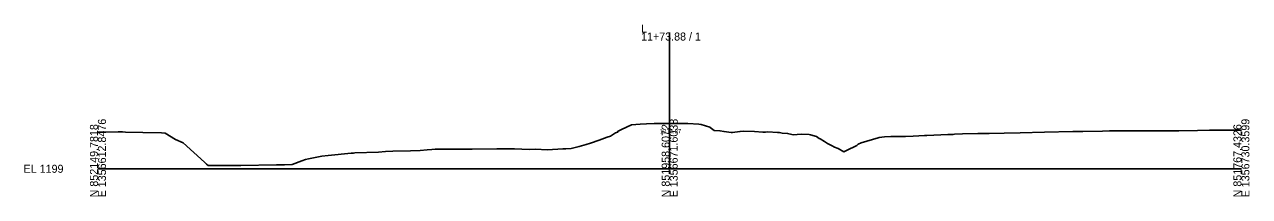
# Model space of a CAD drawing. Extents: x -26 to 4603, y -10 to 4066.
# Drawn here: x 2774.3 to 3202.8, y -9.7 to 50.4 of the extents above; entities that cross this region are included whole.
import ezdxf

# ---------------------------------------------------------------- set-up
doc = ezdxf.new("R2010")
doc.units = 0
for name, color, linetype in [('Exist Cross Section Cell', 7, 'Continuous'), ('Exist XS Center Line Elevation Label', 7, 'Continuous'), ('Exist XS Ground Line', 7, 'Continuous')]:
    doc.layers.add(name, color=color, linetype=linetype)

msp = doc.modelspace()

# ---------------------------------------------------------------- linework, layer by layer
at = {"layer": 'Exist Cross Section Cell'}
for p, q in [((3000, 0), (3000, 47.64)), ((2800, 0), (3000, 0)), ((3000, 0), (3200, 0))]:
    msp.add_line(p, q, dxfattribs=at)
at = {"layer": 'Exist XS Ground Line'}
msp.add_lwpolyline([(2800, 12.76), (2807.09, 12.86), (2807.69, 12.88), (2808.59, 12.87), (2809.67, 12.85), (2815.73, 12.71), (2822.26, 12.54), (2823.51, 12.48), (2827.12, 10.28), (2829.77, 9.06), (2837.31, 2.28), (2837.94, 1.59), (2838.6, 1.12), (2849.94, 1.13), (2862.42, 1.36), (2865.31, 1.41), (2868, 1.45), (2871.3, 2.72), (2872.57, 3.29), (2873.63, 3.45), (2878.33, 4.42), (2880.49, 4.66), (2888.59, 5.45), (2889.38, 5.51), (2889.82, 5.52), (2898.14, 5.85), (2900.58, 6.01), (2903.2, 6.1), (2909.37, 6.24), (2912.75, 6.44), (2915.12, 6.67), (2916.79, 6.79), (2917.93, 6.81), (2922.91, 6.83), (2928.5, 6.81), (2930.95, 6.8), (2939.49, 7), (2940.97, 7.02), (2942.05, 7.02), (2943.57, 6.97), (2945.72, 6.94), (2950.84, 6.71), (2952.92, 6.83), (2957.26, 6.64), (2962.57, 6.92), (2963.68, 6.92), (2965.5, 7.05), (2968.34, 7.84), (2970.78, 8.47), (2972.29, 8.94), (2975.29, 9.98), (2978.17, 11), (2979.25, 11.36), (2981.06, 12.57), (2981.77, 12.78), (2981.97, 13.19), (2983.14, 13.78), (2986.61, 15.39), (2989.65, 15.65), (2991.9, 15.71), (2994.62, 15.83), (2998.58, 15.88), (3000, 15.87), (3002.99, 15.86), (3006.39, 15.83), (3010.16, 15.54), (3011.04, 15.48), (3014.02, 14.51), (3014.17, 14.4), (3015.56, 13.35), (3017.56, 13.32), (3019.04, 13.02), (3020.71, 12.77), (3021.56, 12.68), (3022.03, 12.7), (3024.59, 12.98), (3025.85, 13.19), (3029.66, 13.05), (3032.63, 12.84), (3033.48, 12.85), (3034.29, 12.86), (3037.69, 12.73), (3038.42, 12.72), (3039.39, 12.48), (3041.25, 12.34), (3042.69, 12.03), (3043.24, 11.88), (3045.97, 12.11), (3048.85, 11.97), (3049.26, 11.84), (3051.33, 11.33), (3052.27, 10.59), (3052.69, 10.43), (3054.15, 9.5), (3055.19, 8.82), (3056.82, 8.02), (3057.66, 7.52), (3058.94, 7.06), (3060.91, 5.97), (3061.81, 6.4), (3065.53, 8.11), (3065.96, 8.61), (3067.02, 9.09), (3071, 10.26), (3072.9, 10.84), (3073.34, 10.94), (3075.14, 11.18), (3077.34, 11.24), (3082.48, 11.33), (3085.21, 11.38), (3089.11, 11.59), (3089.96, 11.66), (3097.28, 11.95), (3098.3, 12.01), (3098.71, 12.02), (3099.23, 12.03), (3099.69, 12.04), (3102.39, 12.19), (3107.75, 12.36), (3111.73, 12.38), (3117.03, 12.43), (3122.56, 12.52), (3131.18, 12.77), (3141.02, 13), (3143, 13.02), (3144.57, 13.03), (3151.45, 13.19), (3153.87, 13.23), (3164.51, 13.28), (3168.48, 13.27), (3178.17, 13.28), (3184.65, 13.41), (3188.9, 13.53), (3198.34, 13.55), (3200, 13.55)], dxfattribs=at)

# ---------------------------------------------------------------- texts
at = {"layer": 'Exist Cross Section Cell'}
for s, p in [('11+73.88 / 1', (2990, 44.84)), ('L', (2990, 47.64)), ('EL 1199', (2774, -1.4))]:
    msp.add_text(s, height=2.8, dxfattribs=at).set_placement(p)
for s, p in [('E 1356612.8476', (2802.8, -10)), ('E 1356671.6038', (3002.8, -10)), ('E 1356730.3599', (3202.8, -10)), ('N 852149.7818', (2800, -10)), ('N 851958.6072', (3000, -10)), ('N 851767.4326', (3200, -10))]:
    msp.add_text(s, height=2.8, rotation=90, dxfattribs=at).set_placement(p)
at = {"layer": 'Exist XS Center Line Elevation Label'}
msp.add_text('1214.87', height=1.5, dxfattribs=at).set_placement((2996.54, 12.37))

doc.saveas('drawing.dxf')
